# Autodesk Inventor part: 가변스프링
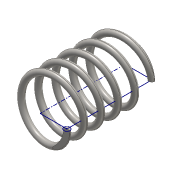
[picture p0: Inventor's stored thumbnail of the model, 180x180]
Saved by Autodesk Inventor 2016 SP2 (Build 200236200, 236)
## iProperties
Created: 2017-12
Part Number: 가변스프링
Material: 스테인레스 스틸
Document SubType Name: Modeling
Designer: Administrator
Density: 8 g/cm^3
Appearance: 반연마
Mass: 6.99592 g
Surface Area: 17.7531 cm^2
Volume: 0.87449 cm^3
Author: Administrator
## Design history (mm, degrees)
sketch "스케치1"
  geometry: L1 (0, 0)-(9, 0); L2 (9, 0)-(9, 28.5); L3 (9, 28.5)-(0, 28.5); L4 (0, 28.5)-(0, 0); C1 r 1 at (9, 0)
  constraints: 8 end point, 2 parallel, 1 centre point, 1 coincident, 1 horizontal, 1 perpendicular
  dimensions: "d0" = 2 diameter of C1; "d1" = 28.5 distance of L1.end L2.end (derived); "d2" = 18 diameter of L2 L4
feature "코일1" pitch "d3" = 10; turns "d5" = 5; dims "d4" = 28.5 (= d1), "d6" = 0, angle "d7" = 90 deg, angle "d8" = 90 deg, "d9" = 0, "d10" = 0
sketch "스케치2"
  geometry: L1 (-10, 0)-(-8, 0) reference; 1 further point
  constraints: 1 horizontal alignment
extrude "돌출1" cut sketch "스케치2" stored distance "d11" = 10; taper "d12" = 0 deg
node "작업 평면1"
sketch "스케치3"
  geometry: L1 (1, 0)-(-1, 0) reference; 1 further point
  constraints: 1 horizontal alignment
extrude "돌출2" cut sketch "스케치3" stored distance "d14" = 10; taper "d15" = 0 deg
node "솔리드1"
node "절단 모서리 투영1"
node "절단 모서리 투영2"
other parameters: "d13" = 90 deg
